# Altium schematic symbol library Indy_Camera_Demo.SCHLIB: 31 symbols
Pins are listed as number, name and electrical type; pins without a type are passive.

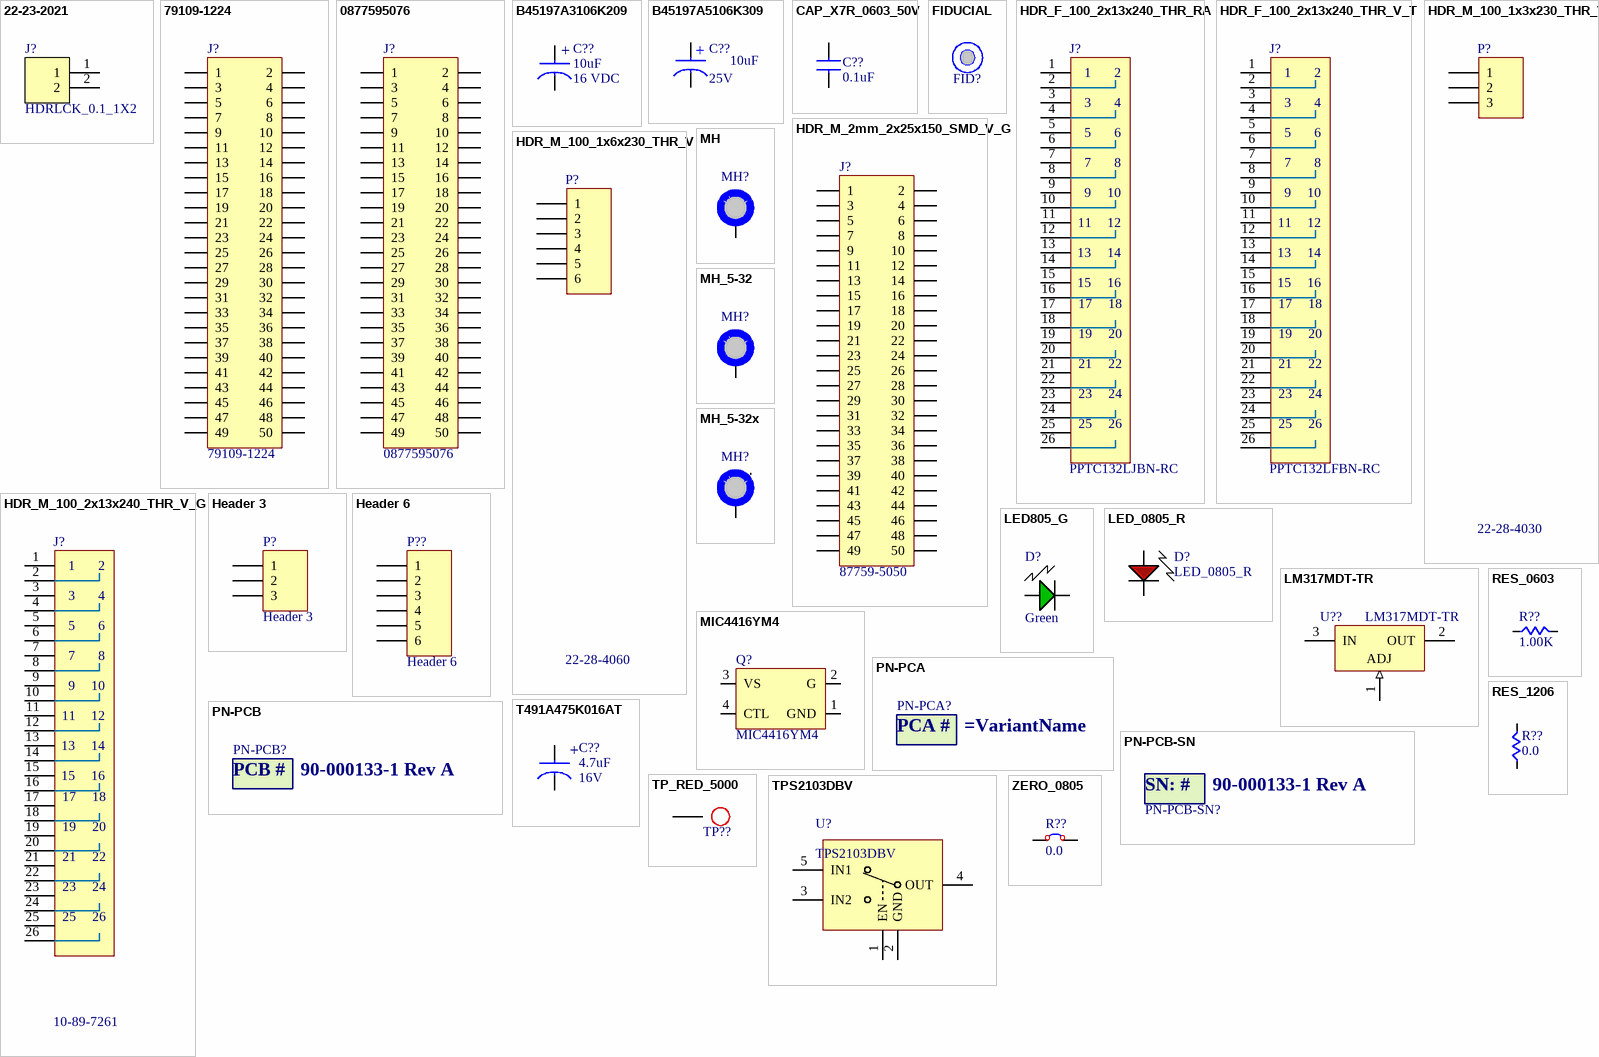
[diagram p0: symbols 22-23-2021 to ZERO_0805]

## 22-23-2021
designator J?, comment HDRLCK_0.1_1X2
CONN HEADER 2POS .100 VERT TIN; Mfg: Molex; User: MikeP; $/100: 0.198500; $/500: 0.158780; $/1000: 0.131790; $/5000: 0.119090; $/ea: 0.340000; Dist1: Digi-Key; Dist1_PN: WM4200-ND; QtyAvail: 33108; ID: 15; PbFree_Status: Unknown
footprint 22-23-2021 (Molex Header, Straight-Friction-Lock, 1x2)
pins: 1, 2

## 79109-1224
designator J?
Female Receptacle, 2x25, 2mm Pitch; Mfg: Molex; User: MikeP
footprint 79109-1224 (Female Receptacle, 2x25, 2mm Pitch)
pins: 1, 2, 3, 4, 5, 6, 7, 8, 9, 10, 11, 12, 13, 14, 15, 16, 17, 18, 19, 20, 21, 22, 23, 24, 25, 26, 27, 28, 29, 30, 31, 32, 33, 34, 35, 36, 37, 38, 39, 40, 41, 42, 43, 44, 45, 46, 47, 48, 49, 50

## 0877595076
designator J?
Male Receptacle, 2x25, 2mm Pitch; Mfg: Molex; User: Oscar
footprint 0877595076 (Male Receptacle, 2x25, 2mm Pitch)
pins: 1, 2, 3, 4, 5, 6, 7, 8, 9, 10, 11, 12, 13, 14, 15, 16, 17, 18, 19, 20, 21, 22, 23, 24, 25, 26, 27, 28, 29, 30, 31, 32, 33, 34, 35, 36, 37, 38, 39, 40, 41, 42, 43, 44, 45, 46, 47, 48, 49, 50

## B45197A3106K209
designator C??, comment Voltage: 16 VDC  (hidden comment: 10uF)
CAP TANT 10UF 16V 10% LOESR SMD; Part_Type: Tantalum; Mfg: EPCOS Inc.; Mfg_PN: B45197A3106K209; Dist1: Digi-Key; Dist1_PN: 495-1676-1-ND; $/100: 0.493200; $/500: 0.389400; $/1000: 0.324500; $/ea: 0.650000; QtyAvail: 2111; Type: capacitor; PbFree_Status: Lead Free; $/10: 0.565000; Mfg_PID: 2969; pref: 100; ID: 2
footprint SMDB
footprint SMD_TAN_B (Capacitor, SM Tantalum; Body 3.5 x 2.8 mm (LxW typ))
pins: 1, 2

## B45197A5106K309
designator C??, comment Voltage: 25V  (hidden comment: 10uF)
CAP TANT 10UF 25V 10% LOESR SMD; Mfg: EPCOS Inc; Mfg_PN: B45197A5106K309; User: Huy; Tolerance: +-10%; ESR: 4.0; Dist1: Digi-Key; Dist1_PN: 495-1565-1-ND; Compliance: RoHS; Type: capacitor; $/100: 0.522500; $/ea: 0.690000; PbFree_Status: Lead Free; QtyAvail: 459; $/10: 0.598000; Mfg_PID: 2970; pref: 100; ID: 2375
signal-integrity model cap
simulation model Cap
footprint SMD_TAN_C (Capacitor, SM Tantalum; Body 6.0 x 3.2 mm (LxW typ))
pins: 1, 2

## CAP_X7R_0603_50V
designator C??, comment 0.1uF
CAP CERAMIC .1UF 50V X7R 0603; Type: capacitor; User: Adam; Mfg_PN: ECJ-1VB1H104K; Dist1: Digi-Key; Dist1_PN: PCC2398CT-ND; Mfg: Panasonic - ECG; PbFree_Status: Lead Free; $/100: 0.058700; $/500: 0.037960; $/1000: 0.024150; ID: 66; Mfg_PID: 1622; QtyAvail: 6730; dist_PID: 1629; dist_pref: 100; $/10: 0.090000; $/ea: 0.000000
footprint 0603
simulation model Cap
signal-integrity model CAP_X7R (Cap)
pins: 1, 2

## FIDUCIAL
designator FID?  (value not drawn)  (no BOM)
Fiducial mark
footprint FIDUCIAL (Fiducial mark)

## HDR_F_100_2x13x240_THR_RA
designator J?, comment PPTC132LJBN-RC
CONN FEMALE 26POS DL .1; Mfg: Sullins Electronics; Dist1_PN: S5527-ND; Dist1: Digi-Key; User: Huy; $/100: 0.925000; $/500: 0.715000; $/1000: 0.665000; $/ea: 1.750000; dist_PID: 4846; dist_pref: 100; ID: 4179; Mfg_PID: 4828; PbFree_Status: Lead free; QtyAvail: 312
footprint HDR_F_100_2x13x240_THR_RA_G_FLIP (Connector; Header; 13x2 Position)
pins: 1 P1, 2 P2, 3 P3, 4 P4, 5 P5, 6 P6, 7 P7, 8 P8, 9 P9, 10 P10, 11 P11, 12 P12, 13 P13, 14 P14, 15 P15, 16 P16, 17 P17, 18 P18, 19 P19, 20 P20, 21 P21, 22 P22, 23 P23, 24 P24, 25 P25, 26 P26

## HDR_F_100_2x13x240_THR_V_T
designator J?, comment PPTC132LFBN-RC
CONN HEADER FMAL 26PS .1" DL TIN; Mfg: Sullins Electronics; Dist1_PN: S7081-ND; Dist1: Digi-Key; User: Oscar
footprint HDR_F_100_2x13x240_THR_V (Footprint not found)
pins: 1 P1, 2 P2, 3 P3, 4 P4, 5 P5, 6 P6, 7 P7, 8 P8, 9 P9, 10 P10, 11 P11, 12 P12, 13 P13, 14 P14, 15 P15, 16 P16, 17 P17, 18 P18, 19 P19, 20 P20, 21 P21, 22 P22, 23 P23, 24 P24, 25 P25, 26 P26

## HDR_M_2mm_2x25x150_SMD_V_G
designator J?, comment 87759-5050
CONN HEADER 50POS 2MM VERT SMD; Mfg: Molex; User: Oscar; Dist1: Digi-Key; Dist1_PN: WM18672-ND
footprint 87759-5050 (Male Receptacle, 2x25, 2mm Pitch)
pins: 1, 2, 3, 4, 5, 6, 7, 8, 9, 10, 11, 12, 13, 14, 15, 16, 17, 18, 19, 20, 21, 22, 23, 24, 25, 26, 27, 28, 29, 30, 31, 32, 33, 34, 35, 36, 37, 38, 39, 40, 41, 42, 43, 44, 45, 46, 47, 48, 49, 50

## HDR_M_100_1x3x230_THR_V
designator P?, comment 22-28-4030
CONN HEADER 3POS .100 VERT TIN; Mfg: Molex; Dist1_PN: WM6403-ND; Dist1: Digi-Key; User: Oscar
footprint HDR_M_100_1x3x230_THR (Connector; Header; 3 Position)
pins: 1, 2, 3

## HDR_M_100_1x6x230_THR_V
designator P?, comment 22-28-4060
CONN HEADER 6POS .100 VERT TIN; Mfg: Molex; Dist1_PN: WM6406-ND; Dist1: Digi-Key; User: Oscar
footprint HDR1X6 (Connector; Header; 6 Position)
pins: 1, 2, 3, 4, 5, 6

## HDR_M_100_2x13x240_THR_V_G
designator J?, comment 10-89-7261
CONN HDR DUAL 26POS .100 SRT TIN; Mfg: Molex; Dist1_PN: WM26926-ND; Dist1: Digi-Key; User: Huy
footprint HDR_M_100_2x13x240_THR_V_G (Connector; Header; 13x2 Position)
pins: 1 P1, 2 P2, 3 P3, 4 P4, 5 P5, 6 P6, 7 P7, 8 P8, 9 P9, 10 P10, 11 P11, 12 P12, 13 P13, 14 P14, 15 P15, 16 P16, 17 P17, 18 P18, 19 P19, 20 P20, 21 P21, 22 P22, 23 P23, 24 P24, 25 P25, 26 P26

## Header 3
designator P?
Header, 3-Pin
footprint HDR1X3 (Connector; Header; 3 Position)
signal-integrity model Connector
pins: 1, 2, 3

## Header 6
designator P??
Header, 6-Pin
footprint HDR1X6 (Connector; Header; 6 Position)
signal-integrity model Connector
pins: 1, 2, 3, 4, 5, 6

## LED805_G
designator D?, comment Green
LED THIN 565NM GRN DIFF 0805 SMD; Mfg: Lumex Opto; Mfg_PN: SML-LXT0805GW-TR; User: MikeP; Dist1: Digi-Key; Dist1_PN: 67-1553-1-ND; Type: general; PbFree_Status: Lead Free
footprint LED805
pins: 1 A, 2 C

## LED_0805_R
designator D?
LED SUPER RED CLEAR 0805 SMD; Mfg: CML Innovative Technologies Inc; Mfg_PN: CMD17-21SRC/TR8; Type: general; Dist1: Digi-Key; Dist1_PN: L62411CT-ND; PbFree_Status: Unknown
footprint LED805
pins: 1 A, 2 C

## LM317MDT-TR
designator U??
IC MED CUR ADJ VOLT REG DPAK; Dist1_PN: 497-1574-1-ND; Mfg: STMicroelectronics; User: Huy; Dist1: Digi-Key; $/100: 0.459000; $/500: 0.314500; $/1000: 0.263500; $/ea: 0.770000; PbFree_Status: Lead Free; QtyAvail: 4576; $/10: 0.612000; Mfg_PID: 2974; pref: 100; ID: 2379
footprint TO-252
pins: 1 ADJ (in), 2 OUT (power), 3 IN (power)

## MH
designator MH?  (value not drawn)  (no BOM)
footprint MH_6-32
footprint MH_6-32
footprint MH125
pins: 0 (power)

## MH_5-32
designator MH?  (value not drawn)  (no BOM)
footprint MH_6-32
footprint MH_6-32
footprint MH_5-32 (MH for screw)
footprint MH_150
pins: 0 (power)

## MH_5-32x
designator MH?  (value not drawn)  (no BOM)
footprint MH_6-32
footprint MH_6-32
footprint MH_5-32x (MH for screw)
footprint MH_150
pins: 0 (power), 1

## MIC4416YM4
designator Q?
IC DRIVER MOSF LOW SIDE SOT143-4; Mfg: Micrel Inc; Dist1_PN: 576-1187-1-ND; Dist1: Digi-Key; User: Huy; Type: general; $/100: 0.860000; $/500: 0.602000; $/ea: 1.290000; ID: 2510; Mfg_PID: 3126; PbFree_Status: Lead Free; QtyAvail: 209
footprint SM/SOT143_1234
pins: 1 GND, 2 G, 3 VS, 4 CTL

## PN-PCA
designator PN-PCA?  (no BOM)
PCA Part number; Mfg: Critical Link, LLC; User: MikeP
footprint PN-PCA (PN-PCA silkscreen)

## PN-PCB
designator PN-PCB?, comment 90-000133-1 Rev A  (mechanical)
PCB Part Number; Mfg: Critical Link, LLC; User: MikeP
footprint PN-PCB (PN-PCB copper)

## PN-PCB-SN
designator PN-PCB-SN?, comment 90-000133-1 Rev A  (no BOM)
PCB Serial Number and Part Number
footprint PN-PCB (PN-PCB cooper)

## RES_0603
designator R??, comment 1.00K
Chip Resistor, 0603, 1/10W; User: Adam; Tolerance: 1%
footprint 0603 (Footprint not found)
simulation model Resistor
signal-integrity model RES (Resistor)
pins: 1, 2

## RES_1206
designator R??, comment 0.0
RES  0.0 OHM 1/4W 5% 1206 SMD; Part_Type: Chip Resistor; Tolerance: 1%; $/10: 0.078000; $/100: 0.042200; $/500: 0.024250; $/1000: 0.016530; $/ea: 0.000000; Dist1: Digi-Key; Dist1_PN: 311-0.0ERCT-ND; Mfg: Yageo Corporation; Mfg_PN: RC1206JR-070RL; PbFree_Status: Lead Free; QtyAvail: 22900; ID: 2324; Mfg_PID: 2909
footprint 1206 (Footprint not found)
simulation model Resistor
signal-integrity model RES (Resistor)
pins: 1, 2

## T491A475K016AT
designator C??, comment 4.7uF  Voltage: 16V
CAPACITOR TANT 4.7UF 16V 10% SMD; Mfg: Kemet; Mfg_PN: T491A475K016AT; Dist1_PN: 399-3697-1-ND; Dist1: Digi-Key; User: Huy; PbFree_Status: Lead Free; $/100: 0.152000; $/500: 0.120000; $/1000: 0.100000; $/ea: 0.200000; ID: 2503; Mfg_PID: 3119; QtyAvail: 3280; dist_PID: 3127; dist_pref: 100
footprint SMD_TAN_A
pins: 1, 2

## TP_RED_5000
designator TP??, comment 5000  (value not drawn)
TEST POINT PC MINI .040; Dist1_PN: 5000K-ND; Mfg: Keystone Electronics; Dist1: Digi-Key; User: Huy; $/100: 0.201100; $/500: 0.183240; $/1000: 0.114400; $/ea: 0.000000; Mfg_PID: 3338; PbFree_Status: Lead Free; pref: 100; QtyAvail: 183450; ID: 2700
footprint keystone_TH_TP (TEST POINT PC MINI .040"D Color keyed)
footprint TP
pins: 1

## TPS2103DBV
designator U?
Power Distribution Switch, 2-In, 1-Out; Mfg: Texas Instruments; User: MikeP
footprint SOT-23-5 (SOT23, 5-Leads, Body 3.0x3.0mm (max), Pitch 0.95mm, IPC High Density)
pins: 1 EN, 2 GND, 3 IN2, 4 OUT, 5 IN1

## ZERO_0805
designator R??, comment 0.0
RES 0.0 OHM 1/10W 5% 0603 SMD; User: MikeP
footprint 0805
pins: 1 TOP, 2 BOT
